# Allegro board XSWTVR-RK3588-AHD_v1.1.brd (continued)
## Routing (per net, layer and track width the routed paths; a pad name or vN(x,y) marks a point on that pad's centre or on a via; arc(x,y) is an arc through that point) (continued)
DGND: length 236.3
  TOP w0.102: ED45.1 61.36,130.42 v1(61.65,130.71) ; 113.82,75.62 114.01,75.62 114.03,75.64 114.45,75.64 114.45,75.64
  TOP w0.127: v1(120.55,44.94) v1(125.59,44.94) 126.71,44.94 127.02,44.63 ; 116.73,42.3 112.74,46.28 ; 21.81,29.3 21.81,28.74
  TOP w0.203: 0.66,104.89 0.61,104.84 0.61,101.31 0.66,101.26 ; 159.12,73.23 159.17,73.18 159.17,68.89 ; 159.17,58.34 159.17,62.4
  TOP w0.254: v1(8.58,82.75) 8.59,82.74 10.31,82.74 ; v1(8.6,84.24) 8.6,84.24 10.31,84.24 ; v1(8.66,87.24) 8.66,87.24 10.31,87.24 ; v1(8.6,85.72) 8.62,85.74 10.31,85.74 ; U23.29 48.6,116.52 U23.4 ; v1(12.01,90.23) 12,90.24 9.54,90.24 J17.17
  TOP w0.305: C314.2 38.43,63.58 R238.2
  TOP w0.381: 38.02,58.69 38.58,59.24 38.58,59.24 C308.2 ; R87.1 v1(141.46,26.79)
  TOP w0.508: R8.1 143.04,75.75 143.05,75.76 ; C2.2 v2(121.81,67.3)
  L3 w0.102: 103.49,42.42 87.16,42.42 87.03,42.29 65.07,42.29 ; 85.74,44.29 85.74,44.29 85.75,44.3 98.15,44.3 98.34,44.1 99.24,44.1 99.42,44.29 99.75,44.29 99.99,44.05 100.78,44.05 101.02,44.29 101.37,44.29 v1(101.48,44.17) 101.6,44.06 102.29,44.06 102.4,44.17 ; 55.45,43.24 102.96,43.24 ; 57.67,41.36 57.81,41.49 105.63,41.49 105.64,41.51 105.67,41.51
  L3 w0.127: 59.14,133.08 59.14,133.08 59.14,125.3 59.18,125.26 ; 121.19,89.86 121.09,89.86 ; 121.19,89.86 120.77,89.44 ; 121.19,89.86 121.36,89.86 ; 121.09,89.86 120.93,89.86 120.83,89.76 ; 121.09,89.86 120.81,89.58 ; 119.9,88.47 119.91,88.47 120.69,89.24 120.74,89.24 121.36,89.86 ; 123.34,94.51 123.34,96.07 123.33,96.08 123.33,96.16 ; 69.66,44.28 83.34,44.28 ; 121.36,89.86 122.98,91.48
  BOTTOM w0.102: 57.72,110.08 51.78,110.08
  BOTTOM w0.127: Q21.2 69.26,34.49 69.26,34.35 69.07,34.15 69.07,33.87 69.08,33.85 ; 58.28,33.54 58.06,33.77 ; 58.28,33.54 58.28,33.93 ; 58.28,33.54 58.28,30.75 58.23,30.69
  BOTTOM w0.508: 47.83,52.36 47.83,51.8 48,51.62 D6.2 ; v2(49.75,28.07) C217.2 ; C155.2 v2(133.38,29.16)
  vias: v1(0.71,154.78) v1(0.71,152.75) v1(0.71,150.72) v1(0.71,148.69) v1(0.71,146.65) v1(0.71,144.62) v1(0.71,142.59) v1(0.71,140.56) v1(0.71,138.53) v1(0.71,136.49) v1(0.71,134.46) v1(0.71,132.43) v1(0.71,130.4) v1(0.71,128.37) v1(0.71,126.33) v1(0.71,124.3) v1(0.71,122.27) v1(0.71,120.24) v1(0.71,118.21) v1(0.71,116.17) v1(0.71,114.14) v1(0.71,112.11) v1(0.71,110.08) v1(0.71,108.05) v1(0.71,99.39) v1(0.71,97.36) v1(0.71,95.33) v1(0.71,93.29) v1(0.71,91.26) v1(0.71,89.23) v1(0.71,87.2) v1(0.71,85.17) v1(0.71,83.13) v1(0.71,81.1) v1(0.71,79.07) v1(0.71,77.04) v1(0.71,75.01) v1(0.71,72.97) v1(0.71,70.94) v1(0.71,68.91) v1(0.71,66.88) v1(0.71,64.85) v1(0.71,62.81) v1(0.71,60.78) v1(0.71,58.75) v1(0.71,56.72) v1(0.71,54.69) v1(0.71,52.65) v1(0.71,50.62) v1(0.71,48.59) v1(0.71,46.56) v1(0.71,44.53) v1(0.71,42.49) v1(0.71,40.46) v1(0.71,38.43) v1(0.71,36.4) v1(0.71,34.37) v1(0.71,32.33) v1(0.71,30.3) v1(0.71,28.27) v1(0.71,26.24) v1(0.71,24.21) v1(0.71,22.17) v1(0.71,20.14) v1(0.71,18.11) v1(0.71,16.08) v1(0.71,14.05) v1(0.71,12.01) v1(0.71,9.98) v1(0.71,7.95) v1(0.71,5.92) v1(0.81,156.81) v1(1.41,1.98) v1(1.9,158.53) v1(2.54,127.61) v1(2.54,125.58) v1(2.54,123.55) v1(2.54,121.52) v1(2.54,119.48) v1(2.66,152.58) v1(2.66,150.55) v1(2.66,148.52) v1(2.66,146.48) v1(2.66,144.45) v1(2.66,142.42) v1(2.76,140.22) v1(2.76,138.19) v1(2.76,136.16) v1(2.76,134.13) v1(2.76,132.1) v1(3.12,117.54) v1(3.09,0.84) v1(3.79,159.28) v1(4.69,150.55) v1(4.69,148.52) v1(4.69,146.48) v1(4.69,144.45) v1(4.69,142.42) v1(4.72,108.53) v1(4.8,140.22) v1(4.8,138.19) v1(4.8,136.16) v1(4.8,134.13) v1(4.8,132.1) v1(5.12,0.71) v1(5.15,117.4) v1(5.82,159.29) v1(5.89,91.2) v1(5.89,89.16) v1(5.89,87.13) v1(5.89,85.1) v1(5.89,83.07) v1(6.42,54.62) v1(6.39,53.61) v1(6.73,152.58) v1(6.73,150.55) v1(6.73,148.52) v1(6.73,146.48) v1(6.73,144.45) v1(6.73,142.42) v1(6.83,140.22) v1(6.83,138.19) v1(6.83,136.16) v1(6.83,134.13) v1(6.83,132.1) v1(6.75,108.53) v1(7.18,117.4) v1(7.15,0.71) v1(7.64,80.54) v1(7.85,159.29) v1(7.89,33.51) v1(8.76,156.64) v1(8.76,154.61) v1(8.76,152.58) v1(8.76,150.55) v1(8.76,148.52) v1(8.76,146.48) v1(8.76,144.45) v1(8.76,142.42) v1(8.78,108.53) v1(8.86,140.22) v1(8.86,138.19) v1(8.86,136.16) v1(8.86,134.13) v1(8.86,132.1) v1(9.22,117.4) v1(9.2,92.84) v1(9.18,0.71) v1(9.67,80.54) v1(9.82,115.46) v1(9.83,55.42) v1(9.88,159.29) v1(10.37,96.35) v1(10.62,53.54) v1(10.79,156.64) v1(10.79,154.61) v1(10.79,152.58) v1(10.79,150.55) v1(10.79,148.52) v1(10.79,146.48) v1(10.79,144.45) v1(10.79,142.42) v1(10.89,140.22) v1(10.89,134.13) v1(10.89,132.1) v1(11.23,92.84) v1(11.3,123.13) v1(11.33,117.4) v1(11.7,80.54) v1(11.79,124.78) v1(11.91,159.29) v1(12.31,99.5) v1(12.36,96.74) v1(12.59,53.05) v1(12.82,156.64) v1(12.82,154.61) v1(12.82,152.58) v1(12.82,150.55) v1(12.82,148.52) v1(12.82,146.48) v1(12.82,144.45) v1(12.82,142.42) v1(12.92,140.22) v1(12.92,134.13) v1(12.92,132.1) v1(12.85,108.53) v1(12.88,91.66) v1(13.12,90.59) v1(13.33,123.13) v1(13.25,0.71) v1(13.36,117.4) v1(13.5,104.11) v1(13.83,124.78) v1(13.79,85.7) v1(13.77,84.21) v1(13.76,82.69) v1(13.81,81.25) v1(13.76,8.1) v1(13.76,7.34) v1(13.76,6.57) v1(13.76,5.81) v1(13.85,87.39) v1(13.95,159.29) v1(14.21,102.21) v1(14.26,8.67) v1(14.39,30.01) v1(14.42,28.94) v1(14.41,27.97) v1(14.47,98.02) v1(14.51,26.61) v1(14.51,25.09) v1(14.51,23.41) v1(14.53,22.4) v1(14.46,20.38) v1(14.63,92.7) v1(14.83,7.34) v1(14.83,6.57) v1(14.83,5.81) v1(14.85,156.64) v1(14.85,154.61) v1(14.85,152.58) v1(14.85,150.55) v1(14.85,148.52) v1(14.85,146.48) v1(14.85,144.45) v1(14.85,142.42) v1(14.91,11.46) v1(14.96,138.19) v1(14.96,134.13) v1(15.04,98.02) v1(15,62.7) v1(15,7.9) v1(15.28,0.71) v1(15.36,123.13) v1(15.4,117.4) v1(15.54,8.44) v1(15.86,124.78) v1(15.9,94.29) v1(15.86,92.18) v1(15.89,91.02) v1(15.9,88.74) v1(15.87,87.67) v1(15.98,159.29) v1(15.95,89.88) v1(16.04,85.68) v1(16.05,82.66) v1(16.11,81.34) v1(16.09,12.11) v1(16.16,41.82) v1(16.26,110.8) v1(16.33,73.69) v1(16.34,35.83) v1(16.41,87.02) v1(16.49,20.38) v1(16.59,84.24) v1(16.61,27.92) v1(16.61,26.61) v1(16.61,25.1) v1(16.73,41.82) v1(16.75,139.68) v1(16.89,156.64) v1(16.89,154.61) v1(16.89,152.58) v1(16.89,150.55) v1(16.89,148.52) v1(16.89,146.48) v1(16.89,144.45) v1(16.89,142.42) v1(16.86,132.83) v1(16.86,130.8) v1(17,13.27) v1(17.07,123.14) v1(17.16,98.48) v1(17.36,137.75) v1(17.41,124.78) v1(17.43,117.4) v1(17.6,81.07) v1(17.57,73.71) v1(17.73,36.17) v1(17.75,61.97) v1(17.81,60.24) v1(17.94,10.06) v1(18.01,159.29) v1(18,77.2) v1(18.11,138.18) v1(18.25,121.29) v1(18.25,119.25) v1(18.29,110.8) v1(18.4,13.94) v1(18.53,27.27) v1(18.52,20.38) v1(18.64,87.05) v1(18.64,85.95) v1(18.65,122.61) v1(18.66,99.8) v1(18.67,36.15) v1(18.92,156.64) v1(18.92,154.61) v1(18.92,152.58) v1(18.92,150.55) v1(18.92,148.52) v1(18.92,146.48) v1(18.92,144.45) v1(18.92,142.42) v1(18.94,82.91) v1(18.94,30.57) v1(18.94,29.45) v1(18.89,28.51) v1(18.96,81.38) v1(19.02,76.27) v1(18.96,26.14) v1(18.96,23.99) v1(18.97,22.92) v1(18.97,21.78) v1(18.99,11.8) v1(19.07,85.52) v1(19.11,84) v1(19.2,96.57) v1(19.32,55.4) v1(19.34,0.71) v1(19.35,53.7) v1(19.66,87.05) v1(19.8,122.59) v1(19.87,64.06) v1(19.92,13.94) v1(20.04,159.29) v1(19.95,82.91) v1(19.97,81.48) v1(20.09,85.52) v1(20.13,84) v1(20.32,110.8) v1(20.35,51.44) v1(20.64,55.38) v1(20.56,27.36) v1(20.55,20.38) v1(20.7,99.8) v1(20.72,63.01) v1(20.77,45.31) v1(20.86,12.58) v1(20.95,156.64) v1(20.95,154.61) v1(20.95,152.58) v1(20.95,150.55) v1(20.95,148.52) v1(20.95,146.48) v1(20.95,144.45) v1(20.95,142.42) v1(21.03,52.52) v1(21.11,85.52) v1(21.14,84) v1(21.19,137.61) v1(21.44,13.94) v1(21.38,0.71) v1(21.51,103.96) v1(21.63,122.53) v1(21.64,81.48) v1(21.77,43.54) v1(21.77,32.63) v1(21.92,77.92) v1(22.03,134.47) v1(21.98,82.91) v1(21.95,76.57) v1(22.01,27.95) v1(22.07,159.29) v1(22.16,84) v1(22.19,66.35) v1(22.16,24.65) v1(22.19,23.42) v1(22.26,22.32) v1(22.35,110.69) v1(22.53,40.88) v1(22.73,99.8) v1(22.7,87.05) v1(22.78,122.56) v1(22.85,82.47) v1(22.88,81.38) v1(22.9,12.58) v1(22.98,156.64) v1(22.98,154.61) v1(22.98,152.58) v1(22.98,150.55) v1(22.98,148.52) v1(22.98,146.48) v1(22.98,144.45) v1(22.98,142.42) v1(23.02,65.45) v1(22.99,53.42) v1(23.04,40.87) v1(22.98,37.27) v1(22.97,13.94) v1(23.05,51.41) v1(23.09,49.7) v1(23.29,30.08) v1(23.4,139) v1(23.41,34.47) v1(23.41,0.71) v1(23.54,103.96) v1(23.57,40.86) v1(23.72,87.05) v1(23.92,122.58) v1(23.87,96.55) v1(23.87,82.47) v1(23.9,81.38) v1(24.01,32.67) v1(24.11,159.29) v1(24.15,85.52) v1(24.49,13.94) v1(24.74,87.05) v1(24.76,99.8) v1(24.91,81.38) v1(24.93,12.58) v1(25.01,156.64) v1(25.01,154.61) v1(25.01,152.58) v1(25.01,150.55) v1(25.01,148.52) v1(25.01,146.48) v1(25.01,144.45) v1(25.02,42.85) v1(25.14,84.01) v1(25.05,40.82) v1(25.19,122.59) v1(25.17,85.52) v1(25.4,28.41) v1(25.42,27.56) v1(25.41,26.74) v1(25.4,22.85) v1(25.44,0.71) v1(25.58,103.96) v1(25.75,87.05) v1(25.83,76.55) v1(25.85,77.87) v1(25.97,127.1) v1(26.02,13.94) v1(26.14,159.29) v1(26.13,84.26) v1(26.19,85.52) v1(26.16,51.09) v1(26.49,67.24) v1(26.5,65.94) v1(26.5,26.75) v1(26.79,99.8) v1(26.77,87.05) v1(26.92,82.47) v1(26.85,22.85) v1(26.96,12.58) v1(27.05,156.64) v1(27.05,154.61) v1(27.05,152.58) v1(27.05,150.55) v1(27.05,148.52) v1(27.05,146.48) v1(27.05,144.45) v1(27.2,85.52) v1(27.15,84.26) v1(27.33,36.42) v1(27.33,34.39) v1(27.42,122.59) v1(27.42,43.91) v1(27.54,13.94) v1(27.47,0.71) v1(27.61,103.96) v1(27.57,26.74) v1(27.73,81.36) v1(27.78,87.05) v1(27.93,82.47) v1(27.86,43.17) v1(27.98,124.64) v1(28,38.34) v1(28.13,49.07) v1(28.17,159.29) v1(28.22,85.52) v1(28.15,84.09) v1(28.42,25.67) v1(28.42,24.15) v1(28.61,75.77) v1(28.65,53.89) v1(28.8,87.05) v1(28.78,51.69) v1(28.8,45.77) v1(28.77,31.58) v1(28.95,82.47) v1(28.98,81.38) v1(28.95,66) v1(28.99,12.58) v1(29.08,156.64) v1(29.08,154.61) v1(29.08,152.58) v1(29.08,150.55) v1(29.08,148.52) v1(29.08,146.48) v1(29.08,144.45) v1(29.14,124.63) v1(29.06,13.94) v1(29.18,122.85) v1(29.23,85.52) v1(29.16,84) v1(29.21,27.42) v1(29.3,44.61) v1(29.49,135.3) v1(29.5,0.71) v1(29.6,55.78) v1(29.73,28.14) v1(29.82,87.05) v1(29.77,21.66) v1(29.96,82.47) v1(30.14,75.58) v1(30.14,53.17) v1(30.14,52.03) v1(30.2,159.29) v1(30.18,84) v1(30.16,55.76) v1(30.25,85.52) v1(30.36,124.65) v1(30.38,122.86) v1(30.41,109.64) v1(30.39,68.02) v1(30.45,50.78) v1(30.59,13.94) v1(30.71,55.77) v1(30.83,87.05) v1(30.75,28.27) v1(30.87,41.21) v1(30.94,37.97) v1(30.86,36.18) v1(30.85,34.73) v1(30.85,33.36) v1(30.86,24.16) v1(30.98,82.47) v1(31.01,81.38) v1(31.02,12.58) v1(31.11,156.64) v1(31.11,154.61) v1(31.11,152.58) v1(31.11,150.55) v1(31.11,148.52) v1(31.11,146.48) v1(31.11,144.45) v1(31.19,84) v1(31.27,85.52) v1(31.32,49.6) v1(31.53,124.65) v1(31.46,75.57) v1(31.58,122.86) v1(31.85,87.05) v1(32,82.47) v1(32.02,81.38) v1(31.96,40.91) v1(32.11,112.37) v1(32.11,13.94) v1(32.23,159.29) v1(32.21,84) v1(32.28,85.52) v1(32.4,65.31) v1(32.73,124.64) v1(32.69,38.16) v1(32.82,122.89) v1(33.01,82.47) v1(33.04,81.38) v1(33.01,8.86) v1(33.01,8.1) v1(33.01,7.34) v1(33.01,6.57) v1(33.01,5.81) v1(33.14,156.64) v1(33.14,154.61) v1(33.14,152.58) v1(33.14,150.55) v1(33.14,148.52) v1(33.14,146.48) v1(33.14,144.45) v1(33.06,12.58) v1(33.22,84) v1(33.3,85.52) v1(33.54,40.86) v1(33.64,13.94) v1(33.57,0.71) v1(33.74,44.08) v1(33.8,75.05) v1(33.92,124.67) v1(34.01,122.89) v1(34.03,82.47) v1(34.06,81.38) v1(34.11,52.92) v1(34.09,33.36) v1(34.07,10.81) v1(34.07,8.86) v1(34.07,8.1) v1(34.07,7.34) v1(34.07,6.57) v1(34.07,5.81) v1(34.24,84) v1(34.27,159.29) v1(34.3,102.92) v1(34.31,85.52) v1(34.67,75.88) v1(34.89,38.07) v1(35.04,40.84) v1(35.09,33.86) v1(35.09,12.58) v1(35.17,156.64) v1(35.17,154.61) v1(35.17,152.58) v1(35.17,150.55) v1(35.17,148.52) v1(35.17,146.48) v1(35.17,144.45) v1(35.18,124.68) v1(35.16,13.94) v1(35.39,55.35) v1(35.73,103.88) v1(35.79,34.63) v1(36.3,159.29) v1(36.41,122.7) v1(36.52,50.55) v1(36.57,40.81) v1(36.68,13.94) v1(37.21,156.64) v1(37.21,154.61) v1(37.21,152.58) v1(37.21,150.55) v1(37.21,148.52) v1(37.21,146.48) v1(37.21,144.45) v1(37.49,36.2) v1(37.62,125.68) v1(37.6,122.94) v1(37.6,37.67) v1(37.63,8.86) v1(37.63,0.71) v1(37.83,58.25) v1(38.03,10.85) v1(38.33,159.29) v1(38.32,36.21) v1(38.39,58.23) v1(38.71,102.85) v1(38.71,72.07) v1(38.69,69.82) v1(38.7,67.31) v1(38.7,65.95) v1(38.84,122.91) v1(38.94,58.24) v1(38.89,37.54) v1(39.24,156.64) v1(39.24,154.61) v1(39.24,152.58) v1(39.24,150.55) v1(39.24,148.52) v1(39.24,146.48) v1(39.24,144.45) v1(39.24,42.1) v1(39.66,0.71) v1(39.98,53.13) v1(40.12,125.9) v1(40.05,11.02) v1(40.36,159.29) v1(40.42,14.28) v1(40.69,37.8) v1(40.76,37.15) v1(40.98,104.89) v1(41.11,54.93) v1(41.19,51.74) v1(41.27,156.64) v1(41.27,154.61) v1(41.27,152.58) v1(41.27,150.55) v1(41.27,148.52) v1(41.27,146.48) v1(41.27,144.45) v1(41.31,38.64) v1(41.7,0.71) v1(41.92,28.04) v1(41.92,26.77) v1(41.92,25.5) v1(41.92,24.23) v1(42.13,55.3) v1(42.08,11.02) v1(42.2,16.37) v1(42.34,125.46) v1(42.39,159.29) v1(43.14,122.62) v1(43.19,28.04) v1(43.19,26.77) v1(43.19,25.5) v1(43.19,24.23) v1(43.3,156.64) v1(43.3,154.61) v1(43.3,152.58) v1(43.3,150.55) v1(43.3,148.52) v1(43.3,146.48) v1(43.3,144.45) v1(43.34,126.3) v1(43.29,46.41) v1(43.73,0.71) v1(44.03,122.6) v1(44.1,11.27) v1(44.43,159.29) v1(44.49,41.05) v1(44.46,28.04) v1(44.46,26.77) v1(44.46,25.5) v1(44.46,24.23) v1(44.46,14.74) v1(45.33,156.64) v1(45.33,154.61) v1(45.33,152.58) v1(45.33,150.55) v1(45.33,148.52) v1(45.33,146.48) v1(45.33,144.45) v1(45.67,42.17) v1(45.73,28.04) v1(45.73,26.77) v1(45.73,25.5) v1(45.73,24.23) v1(45.76,0.71) v1(45.88,117.53) v1(45.9,16.74) v1(46.32,115.65) v1(46.38,100.33) v1(46.39,97.34) v1(46.46,159.29) v1(46.45,140.12) v1(46.47,118.92) v1(46.49,46.23) v1(46.52,41.05) v1(46.58,57.97) v1(47,28.04) v1(47,26.77) v1(47,25.5) v1(47,24.23) v1(47.37,156.64) v1(47.37,154.61) v1(47.37,152.58) v1(47.37,150.55) v1(47.37,148.52) v1(47.37,146.48) v1(47.37,144.45) v1(47.54,41.05) v1(47.57,134.36) v1(47.57,132.33) v1(47.57,130.3) v1(47.57,128.26) v1(47.55,122.96) v1(47.62,48.79) v1(47.62,46.75) v1(47.81,116.87) v1(47.81,115.81) v1(47.79,0.71) v1(47.97,33.87) v1(48.08,140.97) v1(48.43,94.84) v1(48.49,159.29) v1(48.48,97.93) v1(48.52,33.85) v1(48.59,31.69) v1(48.56,16.33) v1(48.69,126.57) v1(48.69,116.87) v1(48.68,115.83) v1(48.77,124.59) v1(48.8,122.96) v1(49.14,33.89) v1(49.29,10.29) v1(49.4,156.64) v1(49.4,154.61) v1(49.4,152.58) v1(49.4,150.55) v1(49.4,148.52) v1(49.4,146.48) v1(49.4,144.45) v1(49.51,116.9) v1(49.49,115.84) v1(50.03,13.87) v1(50.11,140.97) v1(50.08,122.96) v1(50.09,40.12) v1(50.17,44.11) v1(50.52,159.29) v1(50.86,124.83) v1(51.32,123.01) v1(51.43,156.64) v1(51.43,154.61) v1(51.43,152.58) v1(51.43,150.55) v1(51.43,148.52) v1(51.43,146.48) v1(51.43,144.45) v1(51.71,112.07) v1(51.69,46.75) v1(51.69,44.72) v1(51.74,11.74) v1(51.83,41.47) v1(51.86,39.9) v1(51.89,8.77) v1(51.86,0.71) v1(52.14,140.97) v1(52.24,44.24) v1(52.25,8.1) v1(52.25,7.34) v1(52.25,6.57) v1(52.25,5.81) v1(52.35,105.97) v1(52.55,159.29) v1(52.89,9.28) v1(53,124.85) v1(53.32,8.1) v1(53.32,7.34) v1(53.32,6.57) v1(53.32,5.81) v1(53.39,126.92) v1(53.46,156.64) v1(53.46,154.61) v1(53.46,152.58) v1(53.46,150.55) v1(53.46,148.52) v1(53.46,146.48) v1(53.46,144.45) v1(53.46,142.42) v1(53.48,39.85) v1(53.63,41.5) v1(53.66,120.86) v1(53.74,30.22) v1(53.83,43.97) v1(53.88,14.26) v1(53.95,140.04) v1(53.95,126.09) v1(53.97,48.75) v1(53.97,48.2) v1(54.14,16.4) v1(54.11,12.25) v1(54.18,121.64) v1(54.18,120.87) v1(54.29,129.93) v1(54.38,138.05) v1(54.38,136.02) v1(54.38,133.99) v1(54.38,131.96) v1(54.36,105.97) v1(54.42,49.13) v1(54.59,159.29) v1(55.1,49.14) v1(55.15,122.06) v1(55.18,39.83) v1(55.41,127.08) v1(55.4,41.49) v1(55.49,156.64) v1(55.49,154.61) v1(55.49,152.58) v1(55.49,150.55) v1(55.49,148.52) v1(55.49,146.48) v1(55.49,144.45) v1(55.49,142.42) v1(55.47,139.58) v1(55.47,137.55) v1(55.47,135.52) v1(55.47,133.49) v1(55.47,131.45) v1(55.53,124.91) v1(55.76,49.08) v1(56.3,129.6) v1(56.28,105.97) v1(56.33,48.18) v1(56.34,47.62) v1(56.46,120.51) v1(56.62,159.29) v1(56.71,127.68) v1(56.66,126.24) v1(56.9,113.1) v1(56.91,112.42) v1(56.86,40.62) v1(56.92,39.82) v1(57.2,153.31) v1(57.2,151.28) v1(57.2,149.25) v1(57.2,147.21) v1(57.2,145.18) v1(57.2,143.15) v1(57.2,141.12) v1(57.2,139.09) v1(57.2,137.05) v1(57.2,135.02) v1(57.2,132.99) v1(57.2,130.96) v1(57.2,128.93) v1(57.17,47.62) v1(57.19,41.25) v1(57.55,120.83) v1(57.55,118.8) v1(57.76,44.17) v1(57.95,0.71) v1(58.11,151.64) v1(58.11,149.61) v1(58.11,147.58) v1(58.11,145.54) v1(58.11,143.51) v1(58.11,141.48) v1(58.11,139.45) v1(58.1,38.57) v1(58.27,105.97) v1(58.41,154.94) v1(58.42,153.65) v1(58.65,159.29) v1(59.39,109.97) v1(59.44,11.36) v1(59.47,141.18) v1(59.64,61.06) v1(59.64,58.13) v1(59.88,155.06) v1(59.98,0.71) v1(60.16,120.44) v1(60.22,26.74) v1(60.28,105.97) v1(60.68,159.29) v1(60.73,21.13) v1(61.5,141.21) v1(61.67,61.06) v1(61.67,58.13) v1(61.8,109.34) v1(61.91,154.94) v1(61.95,110.45) v1(62.02,0.71) v1(62.13,105.97) v1(62.39,31.07) v1(62.43,20.01) v1(62.43,17.98) v1(62.47,129.99) v1(62.58,128.75) v1(62.58,112.49) v1(63.15,122.88) v1(63.49,11.57) v1(63.7,61.06) v1(64.05,0.71) v1(64.2,105.97) v1(64.3,15.15) v1(64.4,109.3) v1(64.47,25.58) v1(64.62,128.75) v1(64.62,122.65) v1(64.62,120.62) v1(64.62,118.59) v1(64.67,110.46) v1(64.67,38.34) v1(64.76,111.99) v1(64.87,142.4) v1(64.87,140.37) v1(64.87,138.34) v1(64.87,136.31) v1(64.87,134.28) v1(64.87,132.24) v1(65.55,144.53) v1(65.63,33.22) v1(65.73,61.06) v1(65.99,25.7) v1(66.08,0.71) v1(66.21,105.97) v1(66.16,33.24) v1(66.34,38.39) v1(66.65,128.75) v1(66.65,122.65) v1(66.65,120.62) v1(66.65,118.59) v1(66.71,110.46) v1(66.78,159.29) v1(66.75,147.14) v1(66.8,111.99) v1(66.83,26.45) v1(66.91,142.4) v1(66.91,140.37) v1(66.91,138.34) v1(66.91,136.31) v1(66.91,134.28) v1(66.91,132.24) v1(67.18,147.76) v1(67.26,144.51) v1(67.72,148.3) v1(67.83,109.38) v1(67.76,61.06) v1(68.02,105.97) v1(68.01,18.12) v1(68.11,0.71) v1(68.22,147.07) v1(68.26,148.84) v1(68.5,11.89) v1(68.64,38.9) v1(68.68,128.75) v1(68.68,120.62) v1(68.68,118.59) v1(68.74,110.46) v1(68.81,159.29) v1(68.79,149.39) v1(68.76,147.61) v1(68.83,111.99) v1(68.82,33.88) v1(68.84,23.21) v1(68.94,142.4) v1(68.94,140.37) v1(68.94,138.34) v1(68.94,136.31) v1(68.94,134.28) v1(68.94,132.24) v1(69.23,156.93) v1(69.23,155.62) v1(69.22,154.99) v1(69.2,154.38) v1(69.16,150.05) v1(69.28,152.69) v1(69.31,151.73) v1(69.31,150.8) v1(69.3,148.15) v1(69.34,28.16) v1(69.81,148.72) v1(69.8,61.06) v1(70.08,157.17) v1(70.09,105.97) v1(70.2,149.37) v1(70.19,22.31) v1(70.44,150.09) v1(70.35,38.92) v1(70.44,27.26) v1(70.53,153.51) v1(70.53,152.75) v1(70.53,151.99) v1(70.53,151.23) v1(70.53,12.01) v1(70.6,154.97) v1(70.6,154.28) v1(70.68,156.1) v1(70.71,128.75) v1(70.71,124.68) v1(70.71,120.62) v1(70.71,118.59) v1(70.71,37.19) v1(70.84,159.29) v1(70.84,157.27) v1(70.97,142.4) v1(70.97,140.37) v1(70.97,138.34) v1(70.97,136.31) v1(70.97,134.28) v1(70.97,132.24) v1(71.08,13.23) v1(71.44,156.1) v1(71.49,8.1) v1(71.49,7.34) v1(71.49,6.57) v1(71.49,5.81) v1(71.6,157.27) v1(71.83,61.06) v1(71.91,21.94) v1(72.14,149.2) v1(72.13,148.44) v1(72.2,156.1) v1(72.19,147.68) v1(72.17,105.97) v1(72.16,27.26) v1(72.18,0.71) v1(72.36,157.27) v1(72.45,149.9) v1(72.46,34.51) v1(72.48,23.32) v1(72.56,147.01) v1(72.56,8.1) v1(72.56,7.34) v1(72.56,6.57) v1(72.56,5.81) v1(72.74,120.62) v1(72.74,118.59) v1(72.69,11.99) v1(72.87,159.29) v1(72.89,144.47) v1(72.96,156.1) v1(73,142.4) v1(73,140.37) v1(73,138.34) v1(73,136.31) v1(73,134.28) v1(73,132.24) v1(73.13,157.27) v1(73.09,150.32) v1(73.44,149.15) v1(73.35,148.39) v1(73.62,147.68) v1(73.72,156.1) v1(73.72,144.46) v1(73.84,150.49) v1(73.86,61.06) v1(73.89,58.97) v1(73.94,56.9) v1(73.94,54.87) v1(73.94,51.24) v1(73.96,52.95) v1(73.96,50.02) v1(73.99,48.15) v1(74.01,46.24) v1(74.13,105.97) v1(74.16,147.14) v1(74.36,13.09) v1(74.49,156.1) v1(74.48,144.43) v1(74.53,39.09) v1(74.62,150.5) v1(74.65,157.27) v1(74.71,111.83) v1(74.74,110.65) v1(74.78,120.62) v1(74.78,118.59) v1(74.91,159.29) v1(75.01,149.07) v1(75.03,142.4) v1(75.03,140.37) v1(75.03,138.34) v1(75.03,136.31) v1(75.03,134.28) v1(75.03,132.24) v1(75.25,156.1) v1(75.33,23.36) v1(75.36,150.48) v1(75.61,32.66) v1(75.77,144.7) v1(75.89,61.06) v1(76,156.21) v1(76,150.49) v1(76,149.07) v1(76.07,58.95) v1(76.07,56.91) v1(76.07,54.88) v1(76.1,52.97) v1(76.07,51.25) v1(76.1,50.03) v1(76.12,48.17) v1(76.19,105.97) v1(76.15,46.25) v1(76.24,0.71) v1(76.33,148.21) v1(76.39,13.09) v1(76.64,150.5) v1(76.69,23.08) v1(76.77,111.84) v1(76.77,110.65) v1(76.76,11.99) v1(76.94,159.29) v1(77.14,150.89) v1(77.27,148.14) v1(77.44,156.01) v1(77.44,155.25) v1(77.44,154.49) v1(77.44,153.72) v1(77.44,152.96) v1(77.44,152.2) v1(77.44,151.44) v1(77.54,156.76) v1(77.53,140.07) v1(77.5,35.41) v1(77.63,143.88) v1(77.55,34.17) v1(77.73,148.86) v1(77.7,27.02) v1(77.78,149.63) v1(77.92,61.06) v1(77.95,157.4) v1(78.1,58.95) v1(78.1,56.91) v1(78.1,54.88) v1(78.13,52.97) v1(78.1,51.25) v1(78.13,50.03) v1(78.18,105.97) v1(78.15,48.17) v1(78.18,46.25) v1(78.16,17.72) v1(78.32,150.17) v1(78.25,130.36) v1(78.25,128.33) v1(78.25,126.29) v1(78.25,124.26) v1(78.28,32.1) v1(78.27,0.71) v1(78.4,36.37) v1(78.61,157.79) v1(78.8,111.84) v1(78.8,110.65) v1(78.86,155.88) v1(78.86,155.12) v1(78.86,154.35) v1(78.86,153.59) v1(78.86,152.83) v1(78.86,152.07) v1(78.86,151.31) v1(78.86,150.71) v1(78.97,159.29) v1(79.11,39.47) v1(79.42,151.63) v1(79.44,142.95) v1(79.47,150.87) v1(79.49,35.82) v1(79.73,150.16) v1(79.69,130.77) v1(79.72,128.79) v1(79.72,124.73) v1(79.72,120.66) v1(79.72,118.63) v1(79.72,116.6) v1(79.65,40.02) v1(79.96,61.06) v1(80.14,58.95) v1(80.14,56.91) v1(80.14,54.88) v1(80.14,51.25) v1(80.18,149.54) v1(80.23,139.33) v1(80.23,137.3) v1(80.23,135.27) v1(80.23,133.23) v1(80.21,105.97) v1(80.16,52.97) v1(80.16,50.03) v1(80.19,48.17) v1(80.21,46.25) v1(80.18,17.49) v1(80.3,0.71) v1(80.63,148.93) v1(80.84,151.63) v1(80.85,148.2) v1(80.87,147.43) v1(80.87,146.67) v1(80.87,145.91) v1(80.86,145.02) v1(81,159.29) v1(80.96,150.88) v1(81.17,130.02) v1(81.43,150.28) v1(81.76,128.79) v1(81.76,124.73) v1(81.76,120.66) v1(81.76,118.63) v1(81.76,116.6) v1(81.8,38.36) v1(81.86,149.65) v1(81.99,61.06) v1(82.14,148.94) v1(82.13,22.48) v1(82.24,105.97) v1(82.17,58.95) v1(82.17,56.91) v1(82.17,54.88) v1(82.19,52.97) v1(82.17,51.25) v1(82.19,50.03) v1(82.22,48.17) v1(82.24,46.25) v1(82.28,148.19) v1(82.29,147.43) v1(82.29,146.67) v1(82.3,145.96) v1(82.3,144.75) v1(82.26,139.33) v1(82.26,137.3) v1(82.26,135.27) v1(82.26,133.23) v1(82.28,27.02) v1(82.34,0.71) v1(82.74,34.41) v1(83.11,144.76) v1(83.2,130.02) v1(83.31,145.89) v1(83.56,39.31) v1(83.79,128.79) v1(83.79,124.73) v1(83.79,120.66) v1(83.79,118.63) v1(83.79,116.6) v1(84.02,61.06) v1(84.15,105.97) v1(84.2,58.95) v1(84.2,56.91) v1(84.2,54.88) v1(84.22,52.97) v1(84.2,51.25) v1(84.22,50.03) v1(84.15,39.28) v1(84.19,22.42) v1(84.3,141.36) v1(84.3,139.33) v1(84.3,137.3) v1(84.3,135.27) v1(84.3,133.23) v1(84.25,48.17) v1(84.27,46.25) v1(84.32,34.67) v1(84.29,27.09) v1(84.37,0.71) v1(84.66,44.17) v1(85.02,144.79) v1(85.07,159.29) v1(85.23,130.02) v1(85.39,23.38) v1(85.52,154.39) v1(85.51,152.39) v1(85.51,150.36) v1(85.6,148.33) v1(85.6,144.14) v1(85.99,105.97) v1(86.05,61.06) v1(86.23,58.95) v1(86.23,56.91) v1(86.23,54.88) v1(86.24,53.02) v1(86.33,141.36) v1(86.33,139.33) v1(86.33,137.3) v1(86.33,135.27) v1(86.33,133.23) v1(86.31,49.99) v1(86.35,48.17) v1(86.37,46.25) v1(86.4,0.71) v1(86.75,152.37) v1(86.75,150.34) v1(86.82,145.74) v1(86.79,34.18) v1(87.1,159.29) v1(87.14,130.62) v1(87.06,11.21) v1(87.15,155.85) v1(87.59,144.78) v1(87.72,152.13) v1(87.78,155.03) v1(87.85,128.79) v1(87.85,124.73) v1(87.85,120.66) v1(87.85,118.63) v1(87.85,116.6) v1(87.91,111.06) v1(87.86,23.79) v1(87.99,105.97) v1(88.08,61.06) v1(88.09,20.11) v1(88.09,19.42) v1(88.26,58.95) v1(88.26,56.91) v1(88.26,54.88) v1(88.26,53.02) v1(88.36,141.36) v1(88.36,139.33) v1(88.36,137.3) v1(88.36,135.27) v1(88.36,133.23) v1(88.38,48.17) v1(88.4,46.25) v1(88.46,32.73) v1(88.73,14.39) v1(88.85,145.74) v1(89.01,19.04) v1(89.13,159.29) v1(89.08,130.02) v1(89.16,24.26) v1(89.27,151.49) v1(89.25,150.14) v1(89.36,38.05) v1(89.62,144.78) v1(89.65,128.07) v1(89.65,126.04) v1(89.65,124) v1(89.94,111.06) v1(90.12,61.06) v1(90.16,15.82) v1(90.2,11.41) v1(90.3,58.95) v1(90.3,56.91) v1(90.3,54.88) v1(90.31,53.06) v1(90.31,50.04) v1(90.39,141.36) v1(90.39,139.33) v1(90.39,137.3) v1(90.39,135.27) v1(90.39,133.23) v1(90.41,48.17) v1(90.41,46.31) v1(90.46,0.71) v1(90.74,8.1) v1(90.74,7.34) v1(90.74,6.57) v1(90.74,5.81) v1(90.77,118.25) v1(90.91,125.59) v1(90.91,123.56) v1(90.91,121.52) v1(91.34,129.61) v1(91.67,15.13) v1(91.8,8.1) v1(91.8,7.34) v1(91.8,6.57) v1(91.8,5.81) v1(91.94,105.99) v1(91.97,111.06) v1(92.15,61.06) v1(92.19,50.07) v1(92.33,58.95) v1(92.33,56.91) v1(92.33,54.88) v1(92.27,48.11) v1(92.34,46.24) v1(92.42,141.36) v1(92.42,139.33) v1(92.42,137.3) v1(92.42,133.23) v1(92.42,25.58) v1(92.63,118.07) v1(92.81,128.21) v1(92.99,28.98) v1(93.65,115.37) v1(94.01,111.06) v1(93.97,105.99) v1(94.1,130.32) v1(94.12,52.89) v1(94.12,50.85) v1(94.18,61.06) v1(94.19,58.94) v1(94.18,56.91) v1(94.18,54.91) v1(94.15,48.94) v1(94.17,47) v1(94.46,141.36) v1(94.46,139.33) v1(94.46,137.3) v1(94.83,128.42) v1(95.23,159.29) v1(95.2,143.43) v1(95.45,156.41) v1(95.45,154.38) v1(95.45,152.35) v1(95.45,129.99) v1(95.45,125.93) v1(95.45,123.9) v1(96.04,111.06) v1(96,105.99) v1(96.2,56.94) v1(96.2,54.91) v1(96.15,52.89) v1(96.15,50.85) v1(96.18,48.94) v1(96.2,47) v1(96.52,112.5) v1(96.56,0.71) v1(96.88,35.93) v1(96.99,11.97) v1(97.26,159.29) v1(97.4,143.94) v1(97.4,141.9) v1(97.4,139.87) v1(97.4,137.84) v1(97.4,135.81) v1(97.4,133.78) v1(97.4,125.65) v1(97.4,123.62) v1(97.4,121.58) v1(97.4,119.55) v1(97.4,117.52) v1(97.48,156.41) v1(97.48,154.38) v1(97.48,152.35) v1(97.48,148.28) v1(97.96,111.06) v1(98.04,105.99) v1(98.24,56.94) v1(98.24,54.91) v1(98.19,52.89) v1(98.19,50.85) v1(98.21,48.94) v1(98.24,47) v1(98.38,112.33) v1(98.59,0.71) v1(98.88,16.55) v1(99.29,159.29) v1(99.52,156.41) v1(99.52,154.38) v1(99.52,152.35) v1(99.52,148.28) v1(99.52,146.25) v1(99.52,144.22) v1(99.52,142.19) v1(99.52,140.15) v1(99.52,138.12) v1(99.52,136.09) v1(99.52,134.06) v1(99.52,132.03) v1(99.52,127.96) v1(99.52,125.93) v1(99.52,123.9) v1(99.52,121.87) v1(99.52,119.83) v1(99.52,117.8) v1(99.52,115.28) v1(99.71,112.48) v1(100.03,11.97) v1(100.07,105.99) v1(100.22,52.89) v1(100.22,50.85) v1(100.24,48.94) v1(100.26,111.55) v1(100.27,56.94) v1(100.27,54.91) v1(100.27,47) v1(100.64,15.54) v1(100.62,0.71) v1(101.07,26.7) v1(101.07,25.43) v1(101.07,24.16) v1(101.07,22.89) v1(101.07,21.62) v1(101.07,20.35) v1(101.32,159.29) v1(101.44,45.23) v1(101.44,13.61) v1(101.55,156.41) v1(101.55,154.38) v1(101.55,152.35) v1(101.55,150.31) v1(101.55,148.28) v1(101.55,146.25) v1(101.55,144.22) v1(101.55,142.19) v1(101.55,140.15) v1(101.55,138.12) v1(101.55,136.09) v1(101.55,134.06) v1(101.55,132.03) v1(101.55,129.99) v1(101.55,127.96) v1(101.55,125.93) v1(101.55,123.9) v1(101.55,121.87) v1(101.55,119.83) v1(101.55,117.8) v1(101.55,115.28) v1(101.74,112.48) v1(102.1,105.99) v1(102.29,111.55) v1(102.25,52.89) v1(102.25,50.85) v1(102.25,48.99) v1(102.28,47.05) v1(102.34,26.7) v1(102.34,25.43) v1(102.34,24.16) v1(102.34,22.89) v1(102.34,21.62) v1(102.34,20.35) v1(102.41,35.77) v1(102.67,15.54) v1(102.66,0.71) v1(103.08,11.97) v1(103.35,159.29) v1(103.58,156.41) v1(103.58,154.38) v1(103.58,152.35) v1(103.58,150.31) v1(103.58,148.28) v1(103.58,146.25) v1(103.58,144.22) v1(103.58,142.19) v1(103.58,140.15) v1(103.58,138.12) v1(103.58,136.09) v1(103.58,134.06) v1(103.58,132.03) v1(103.58,129.99) v1(103.58,127.96) v1(103.58,125.93) v1(103.58,123.9) v1(103.58,121.87) v1(103.58,119.83) v1(103.58,117.8) v1(103.58,115.28) v1(103.59,45.28) v1(103.61,44.12) v1(103.61,26.7) v1(103.61,25.43) v1(103.61,24.16) v1(103.61,22.89) v1(103.61,21.62) v1(103.61,20.35) v1(104.13,105.99) v1(104.36,50.88) v1(104.38,48.96) v1(104.41,47.02) v1(104.7,15.54) v1(104.69,0.71) v1(104.88,26.7) v1(104.88,25.43) v1(104.88,24.16) v1(104.88,22.89) v1(104.88,21.62) v1(104.88,20.35) v1(105.39,159.29) v1(105.44,12.47) v1(105.52,45.29) v1(105.61,156.41) v1(105.61,154.38) v1(105.61,152.35) v1(105.61,150.31) v1(105.61,148.28) v1(105.61,146.25) v1(105.61,144.22) v1(105.61,142.19) v1(105.61,140.15) v1(105.61,138.12) v1(105.61,136.09) v1(105.61,125.93) v1(105.61,123.9) v1(105.61,121.87) v1(105.61,119.83) v1(105.61,117.8) v1(105.64,115.24) v1(105.6,111.68) v1(105.57,44.1) v1(105.91,62.34) v1(105.88,35.79) v1(106.15,26.7) v1(106.15,25.43) v1(106.15,24.16) v1(106.15,22.89) v1(106.15,21.62) v1(106.15,20.35) v1(106.39,50.88) v1(106.41,48.96) v1(106.44,47.02) v1(106.4,9.72) v1(106.67,16.06) v1(106.72,0.71) v1(106.99,93.72) v1(106.99,87.34) v1(106.98,63.92) v1(107.05,101.3) v1(107.05,99.33) v1(107.05,79.38) v1(107.05,72.37) v1(107.42,159.29) v1(107.42,26.7) v1(107.42,25.43) v1(107.42,24.16) v1(107.42,22.89) v1(107.42,21.62) v1(107.42,20.35) v1(107.54,45.33) v1(107.47,41.32) v1(107.64,156.41) v1(107.64,154.38) v1(107.64,152.35) v1(107.64,150.31) v1(107.64,148.28) v1(107.64,146.25) v1(107.64,144.22) v1(107.64,125.93) v1(107.64,123.9) v1(107.64,121.87) v1(107.64,119.83) v1(107.64,117.8) v1(107.63,111.68) v1(107.6,44.13) v1(107.66,142.25) v1(107.66,140.22) v1(107.66,138.18) v1(107.67,115.24) v1(107.76,136.24) v1(107.78,14.11) v1(107.78,13.63) v1(108.28,34.07) v1(108.27,31.79) v1(108.34,14.12) v1(108.42,50.88) v1(108.42,49.02) v1(108.35,13.64) v1(108.43,9.72) v1(108.45,47.08) v1(109.04,76.96) v1(109.04,74.93) v1(109.03,66.92) v1(109.06,81.03) v1(109.05,79) v1(109.45,159.29) v1(109.62,144.25) v1(109.68,156.41) v1(109.68,154.38) v1(109.68,152.35) v1(109.68,150.31) v1(109.68,148.28) v1(109.68,146.25) v1(109.69,142.25) v1(109.69,140.22) v1(109.69,138.18) v1(109.68,125.93) v1(109.68,123.9) v1(109.68,121.87) v1(109.68,119.83) v1(109.68,117.8) v1(109.7,115.24) v1(109.69,111.64) v1(109.79,136.24) v1(109.98,7.34) v1(109.98,6.57) v1(109.98,5.81) v1(110.24,39.67) v1(110.23,39.16) v1(110.39,7.98) v1(110.52,34.04) v1(110.51,14.08) v1(110.46,9.72) v1(110.62,31.53) v1(110.78,0.71) v1(111.08,109.66) v1(111.05,6.57) v1(111.05,5.81) v1(111.24,7.31) v1(111.34,144.53) v1(111.48,159.29) v1(111.53,43.09) v1(111.64,89.58) v1(111.71,156.41) v1(111.71,154.38) v1(111.71,152.35) v1(111.71,150.31) v1(111.71,148.28) v1(111.71,146.25) v1(111.72,142.25) v1(111.72,140.22) v1(111.72,138.18) v1(111.69,136.36) v1(111.71,125.93) v1(111.71,123.9) v1(111.71,121.87) v1(111.71,119.83) v1(111.71,117.8) v1(111.68,47.63) v1(111.73,39.61) v1(111.79,24.78) v1(111.88,103.29) v1(112.05,46.93) v1(112.13,45.51) v1(112.07,21.8) v1(112.17,49.35) v1(112.2,25.56) v1(112.44,104.94) v1(112.4,48.5) v1(112.5,53.15) v1(112.57,54.91) v1(112.61,40.87) v1(112.7,88.68) v1(112.73,50.54) v1(112.81,37.45) v1(112.94,112.65) v1(112.9,12.65) v1(113.14,109.62) v1(113.08,22.06) v1(113.24,101.49) v1(113.18,99.22) v1(113.3,107.79) v1(113.37,144.53) v1(113.51,159.29) v1(113.47,23.1) v1(113.57,75.68) v1(113.56,43.09) v1(113.74,156.41) v1(113.74,154.38) v1(113.74,152.35) v1(113.74,150.31) v1(113.74,148.28) v1(113.74,146.25) v1(113.72,136.36) v1(113.74,125.93) v1(113.74,123.9) v1(113.74,121.87) v1(113.74,119.83) v1(113.74,117.8) v1(113.71,95.14) v1(113.74,17.42) v1(113.75,142.25) v1(113.75,140.22) v1(113.75,138.18) v1(113.76,91.61) v1(113.76,25.27) v1(113.86,82.11) v1(113.88,40.2) v1(113.86,37.79) v1(113.87,11.64) v1(114.1,58.29) v1(114.16,34.49) v1(114.19,33.56) v1(114.21,21.83) v1(114.37,111.21) v1(114.39,27.92) v1(114.41,23.13) v1(114.5,53.35) v1(114.45,49.54) v1(114.51,26.43) v1(114.46,25.28) v1(114.59,28.9) v1(114.8,98.79) v1(114.77,27.2) v1(114.85,42.49) v1(114.91,13.46) v1(114.85,0.71) v1(114.97,83.84) v1(115.03,37.81) v1(115.15,102.2) v1(115.4,144.53) v1(115.36,107.75) v1(115.36,26.52) v1(115.47,51.56) v1(115.45,50.07) v1(115.55,159.29) v1(115.61,75.68) v1(115.69,136.23) v1(115.72,59.52) v1(115.68,57.22) v1(115.7,55.38) v1(115.72,53.42) v1(115.67,17.35) v1(115.77,156.41) v1(115.77,154.38) v1(115.77,152.35) v1(115.77,150.31) v1(115.77,148.28) v1(115.77,146.25) v1(115.75,142.28) v1(115.75,140.19) v1(115.81,138.03) v1(115.77,125.93) v1(115.77,123.9) v1(115.77,121.87) v1(115.77,119.83) v1(115.77,117.8) v1(115.81,109.77) v1(115.78,106.23) v1(115.78,104.2) v1(115.86,12.06) v1(116.03,83.34) v1(115.95,49.59) v1(116.08,94.03) v1(116.11,92.07) v1(116.09,29.04) v1(116.22,33.56) v1(116.19,21.55) v1(116.34,112.74) v1(116.26,20.06) v1(116.26,18.41) v1(116.35,112.3) v1(116.35,111.84) v1(116.38,88.28) v1(116.43,41.21) v1(116.68,38.5) v1(116.83,112.75) v1(116.84,112.31) v1(116.84,111.85) v1(116.88,0.71) v1(117,108.13) v1(117,106.1) v1(117,104.07) v1(117,102.03) v1(117,100) v1(117,97.97) v1(116.98,48.66) v1(117.15,34.22) v1(117.2,13.46) v1(117.44,144.53) v1(117.5,136.36) v1(117.5,134.32) v1(117.5,132.29) v1(117.46,109.02) v1(117.46,106.99) v1(117.46,104.96) v1(117.46,102.92) v1(117.46,100.89) v1(117.52,30.47) v1(117.52,21.92) v1(117.58,159.29) v1(117.61,9.05) v1(117.66,111.04) v1(117.69,41.72) v1(117.7,26.18) v1(117.8,156.41) v1(117.8,154.38) v1(117.8,152.35) v1(117.8,150.31) v1(117.8,148.28) v1(117.8,146.25) v1(117.78,142.28) v1(117.8,140.15) v1(117.8,138.12) v1(117.8,129.99) v1(117.8,127.96) v1(117.8,125.93) v1(117.8,123.9) v1(117.8,121.87) v1(117.8,117.8) v1(117.75,25.06) v1(117.75,23.54) v1(117.85,48.08) v1(117.94,32.46) v1(117.89,12.06) v1(118,38.53) v1(118.13,40.1) v1(118.21,95.9) v1(118.45,42.46) v1(118.58,64.85) v1(118.65,90.45) v1(118.71,63.28) v1(118.67,34.15) v1(118.72,13.46) v1(118.83,99.91) v1(118.91,0.71) v1(119.01,46.57) v1(119.09,86.52) v1(119.1,85.15) v1(119.24,92.4) v1(119.31,43.2) v1(119.47,144.53) v1(119.49,110.62) v1(119.49,38.42) v1(119.61,159.29) v1(119.84,156.41) v1(119.84,154.38) v1(119.84,152.35) v1(119.84,150.31) v1(119.84,148.28) v1(119.84,146.25) v1(119.84,140.15) v1(119.84,138.12) v1(119.84,136.09) v1(119.84,134.06) v1(119.84,132.03) v1(119.84,129.99) v1(119.84,127.96) v1(119.84,125.93) v1(119.84,123.9) v1(119.85,47.72) v1(119.85,45.68) v1(119.93,12.06) v1(120.06,43.95) v1(120.31,84.3) v1(120.25,34.72) v1(120.43,121.13) v1(120.6,65.11) v1(120.86,99.91) v1(120.94,79.92) v1(120.94,0.71) v1(121.14,141.86) v1(121.19,60.84) v1(121.47,111.04) v1(121.64,159.29) v1(121.77,13.46) v1(121.87,156.41) v1(121.87,154.38) v1(121.87,152.35) v1(121.87,150.31) v1(121.87,148.28) v1(121.87,146.25) v1(121.87,144.22) v1(121.87,121.87) v1(121.92,95.06) v1(121.93,91.47) v1(122.01,93.32) v1(122.02,79.92) v1(122.02,38.05) v1(121.96,12.06) v1(122.13,36.37) v1(122.57,141.95) v1(122.58,139.92) v1(122.58,137.89) v1(122.58,135.86) v1(122.58,133.83) v1(122.58,131.79) v1(122.58,129.76) v1(122.58,37.7) v1(123.03,126.23) v1(122.98,0.71) v1(123.08,79.91) v1(123.29,110.62) v1(123.3,13.46) v1(123.64,93.29) v1(123.64,38.02) v1(123.67,159.29) v1(123.84,40.1) v1(123.9,156.41) v1(123.9,154.38) v1(123.9,152.35) v1(123.9,150.31) v1(123.9,148.28) v1(123.9,146.25) v1(123.9,144.22) v1(123.9,142.19) v1(123.9,140.15) v1(123.9,138.12) v1(123.9,136.09) v1(123.9,134.06) v1(123.9,132.03) v1(123.9,129.99) v1(123.9,127.96) v1(123.9,123.9) v1(123.9,121.87) v1(123.99,12.06) v1(124.14,79.91) v1(124.32,118.99) v1(124.52,126.36) v1(124.47,124.79) v1(124.6,14) v1(124.68,99.91) v1(124.72,41.07) v1(124.8,93.91) v1(125.03,39.25) v1(125.01,0.71) v1(125.18,82.18) v1(125.19,16.06) v1(125.29,110.94) v1(125.29,42) v1(125.28,12.58) v1(125.71,159.29) v1(125.82,13.11) v1(125.93,156.41) v1(125.93,154.38) v1(125.93,152.35) v1(125.93,150.31) v1(125.93,148.28) v1(125.93,146.25) v1(125.93,144.22) v1(125.93,142.19) v1(125.93,140.15) v1(125.93,138.12) v1(125.93,136.09) v1(125.93,134.06) v1(125.93,132.03) v1(125.93,129.99) v1(125.93,127.96) v1(125.93,125.93) v1(125.91,123.36) v1(125.94,42.86) v1(125.96,124.92) v1(126.03,39.72) v1(126.3,43.9) v1(126.35,82.21) v1(126.36,13.65) v1(126.52,95.08) v1(126.67,29.78) v1(126.67,28.51) v1(126.67,27.24) v1(126.67,25.97) v1(126.67,24.7) v1(126.69,14.34) v1(126.83,79.88) v1(126.83,40.44) v1(126.89,11.94) v1(126.99,79.33) v1(126.98,77.89) v1(127.23,93.56) v1(127.29,121.87) v1(127.4,123.48) v1(127.42,110.62) v1(127.6,77.86) v1(127.63,41.18) v1(127.74,159.29) v1(127.94,29.78) v1(127.94,28.51) v1(127.94,27.24) v1(127.94,25.97) v1(127.94,24.7) v1(127.96,156.41) v1(127.96,154.38) v1(127.96,152.35) v1(127.96,150.31) v1(127.96,148.28) v1(127.96,146.25) v1(127.96,144.22) v1(127.96,142.19) v1(127.96,140.15) v1(127.96,138.12) v1(127.96,136.09) v1(127.96,134.06) v1(127.96,132.03) v1(127.96,129.99) v1(127.96,127.96) v1(127.96,125.93) v1(127.96,123.9) v1(127.96,117.8) v1(128.08,13.24) v1(128.43,41.9) v1(128.5,99.91) v1(128.91,16.77) v1(128.91,14.48) v1(128.87,12.02) v1(129.03,77.64) v1(128.98,17.33) v1(129.07,0.71) v1(129.21,29.78) v1(129.21,28.51) v1(129.21,27.24) v1(129.21,25.97) v1(129.21,24.7) v1(129.22,8.1) v1(129.22,7.34) v1(129.22,6.57) v1(129.22,5.81) v1(129.49,41.94) v1(129.52,18.4) v1(129.71,95.94) v1(129.77,159.29) v1(130,156.41) v1(130,154.38) v1(130,152.35) v1(130,150.31) v1(130,148.28) v1(130,146.25) v1(130,144.22) v1(130,142.19) v1(130,140.15) v1(130,138.12) v1(130,136.09) v1(130,134.06) v1(130,132.03) v1(130,129.99) v1(130,127.96) v1(130,125.93) v1(130,123.9) v1(130,121.87) v1(130,117.8) v1(129.99,13.02) v1(130.29,7.34) v1(130.29,6.57) v1(130.29,5.81) v1(130.38,16.73) v1(130.38,14.44) v1(130.48,29.78) v1(130.48,28.51) v1(130.48,27.24) v1(130.48,25.97) v1(130.48,24.7) v1(130.62,111.28) v1(130.64,81.08) v1(130.61,8.02) v1(130.77,17.87) v1(130.88,33.71) v1(131.17,80.99) v1(131.18,80.35) v1(131.15,8.56) v1(131.43,90.81) v1(131.43,86.67) v1(131.41,11.38) v1(131.63,91.61) v1(131.8,159.29) v1(131.75,29.78) v1(131.75,28.51) v1(131.75,27.24) v1(131.75,25.97) v1(131.75,24.7) v1(132.03,156.41) v1(132.03,154.38) v1(132.03,152.35) v1(132.03,150.31) v1(132.03,148.28) v1(132.03,146.25) v1(132.03,144.22) v1(132.03,142.19) v1(132.03,140.15) v1(132.03,138.12) v1(132.03,136.09) v1(132.03,134.06) v1(132.03,132.03) v1(132.03,129.99) v1(132.03,127.96) v1(132.03,125.93) v1(132.03,123.9) v1(132.03,121.87) v1(131.96,17.75) v1(132.31,99.91) v1(132.27,92.56) v1(132.4,33.96) v1(132.35,17.16) v1(132.53,90.82) v1(132.49,86.66) v1(132.62,83.96) v1(132.62,83) v1(132.57,12.26) v1(132.65,111.28) v1(132.83,16.57) v1(132.96,113.29) v1(133.07,33.95) v1(133.53,90.88) v1(133.56,109.64) v1(133.56,107.61) v1(133.56,105.58) v1(133.56,103.55) v1(133.56,101.52) v1(133.55,86.65) v1(133.69,33.92) v1(133.83,159.29) v1(133.84,83.54) v1(134.01,85.56) v1(134.06,156.41) v1(134.06,154.38) v1(134.06,152.35) v1(134.06,150.31) v1(134.06,148.28) v1(134.06,146.25) v1(134.06,144.22) v1(134.06,142.19) v1(134.06,140.15) v1(134.06,138.12) v1(134.06,136.09) v1(134.06,134.06) v1(134.06,132.03) v1(134.06,129.99) v1(134.06,127.96) v1(134.06,125.93) v1(134.06,123.9) v1(134.06,121.87) v1(134.06,117.8) v1(134.16,90.8) v1(134.24,86.66) v1(134.28,16.67) v1(135.24,86.65) v1(135.17,0.71) v1(135.82,60.66) v1(135.76,20.67) v1(135.87,159.29) v1(135.92,87.79) v1(136.02,90.73) v1(136,89.77) v1(136.02,88.74) v1(135.98,87.35) v1(136.09,156.41) v1(136.09,154.38) v1(136.09,152.35) v1(136.09,150.31) v1(136.09,148.28) v1(136.09,146.25) v1(136.09,144.22) v1(136.09,142.19) v1(136.09,140.15) v1(136.09,138.12) v1(136.09,136.09) v1(136.09,134.06) v1(136.09,125.93) v1(136.09,123.9) v1(136.09,121.87) v1(136.09,117.8) v1(136.75,72.45) v1(137.2,0.71) v1(137.9,159.29) v1(137.97,80.07) v1(138.12,156.41) v1(138.12,154.38) v1(138.12,152.35) v1(138.12,150.31) v1(138.12,148.28) v1(138.12,146.25) v1(138.12,144.22) v1(138.09,142.16) v1(138.09,140.13) v1(138.09,138.14) v1(138.09,136.11) v1(138.12,125.93) v1(138.12,123.9) v1(138.12,121.87) v1(138.12,117.8) v1(138.59,16.21) v1(138.72,69.52) v1(138.79,72.09) v1(139.2,81.69) v1(139.23,0.71) v1(139.55,111.18) v1(139.6,109.15) v1(139.6,107.12) v1(139.6,105.08) v1(139.6,103.05) v1(139.6,101.02) v1(139.55,98.99) v1(139.93,159.29) v1(139.87,90.26) v1(140.13,142.16) v1(140.13,140.13) v1(140.13,138.14) v1(140.13,136.11) v1(140.12,96.68) v1(140.16,156.41) v1(140.16,154.38) v1(140.16,152.35) v1(140.16,150.31) v1(140.16,148.28) v1(140.16,146.25) v1(140.16,144.22) v1(140.16,125.93) v1(140.16,123.9) v1(140.16,121.87) v1(140.16,117.8) v1(140.42,78.31) v1(140.39,27.93) v1(140.51,36.06) v1(140.51,34.02) v1(140.51,29.96) v1(141.12,37.99) v1(141.33,85.8) v1(141.26,0.71) v1(141.38,110.76) v1(141.35,92.47) v1(141.56,73.31) v1(141.73,56.58) v1(141.87,67.83) v1(141.96,159.29) v1(142.05,144.11) v1(142.05,142.08) v1(142.05,140.04) v1(142.19,156.41) v1(142.19,154.38) v1(142.19,152.35) v1(142.19,150.31) v1(142.19,148.28) v1(142.19,146.25) v1(142.18,138.15) v1(142.19,136.09) v1(142.19,125.93) v1(142.19,123.9) v1(142.19,121.87) v1(142.19,117.8) v1(142.23,93.08) v1(142.23,35.36) v1(142.23,33.32) v1(142.25,18.57) v1(142.25,16.54) v1(142.41,99.89) v1(142.41,79.19) v1(142.45,78.31) v1(142.57,73.64) v1(142.85,85.94) v1(143.05,79.85) v1(143.08,13.63) v1(143.19,86.25) v1(143.31,84.84) v1(143.3,0.71) v1(143.36,111.18) v1(143.62,20.08) v1(143.86,9.2) v1(143.99,159.29) v1(143.97,96.68) v1(144.08,144.11) v1(144.08,142.08) v1(144.08,140.04) v1(144.14,79.87) v1(144.22,156.41) v1(144.22,154.38) v1(144.22,152.35) v1(144.22,150.31) v1(144.22,148.28) v1(144.22,146.25) v1(144.22,138.12) v1(144.22,136.09) v1(144.22,125.93) v1(144.22,123.9) v1(144.22,121.87) v1(144.22,117.8) v1(144.25,93.26) v1(144.94,94.01) v1(144.9,30.5) v1(145.13,79.86) v1(145.15,85.71) v1(145.33,0.71) v1(145.5,110.95) v1(145.65,51.3) v1(145.65,20.08) v1(145.79,56.55) v1(145.89,9.26) v1(146.03,159.29) v1(146.11,144.11) v1(146.11,142.08) v1(146.11,140.04) v1(146.21,79.84) v1(146.25,156.41) v1(146.25,154.38) v1(146.25,152.35) v1(146.25,150.31) v1(146.25,148.28) v1(146.25,146.25) v1(146.26,41.85) v1(146.45,138.15) v1(146.48,60.82) v1(146.59,99.89) v1(146.63,94.33) v1(146.67,73.69) v1(146.71,55.87) v1(146.68,37.49) v1(146.79,136.14) v1(146.91,57.89) v1(146.93,30.5) v1(147.14,75.82) v1(147.2,122.08) v1(147.19,111.19) v1(147.33,118.02) v1(147.3,82.3) v1(147.37,94.32) v1(147.68,51.22) v1(147.68,20.08) v1(147.77,96.66) v1(148.06,159.29) v1(148.15,144.11) v1(148.15,142.08) v1(148.15,140.04) v1(148.28,156.41) v1(148.28,154.38) v1(148.28,152.35) v1(148.28,150.31) v1(148.28,148.28) v1(148.28,146.25) v1(148.28,136.09) v1(148.29,95.07) v1(148.29,41.85) v1(148.4,99.46) v1(148.36,82.3) v1(148.39,77.96) v1(148.47,122.43) v1(148.47,118.37) v1(148.46,8.1) v1(148.46,7.34) v1(148.46,6.57) v1(148.46,5.81) v1(148.71,37.49) v1(148.87,82.95) v1(149.01,93.64) v1(148.96,30.5) v1(149.3,110.92) v1(149.38,43.56) v1(149.39,0.71) v1(149.53,8.1) v1(149.53,7.34) v1(149.53,6.57) v1(149.53,5.81) v1(150.09,159.29) v1(150.32,156.41) v1(150.32,154.38) v1(150.32,152.35) v1(150.32,150.31) v1(150.32,148.28) v1(150.32,146.25) v1(150.32,142.19) v1(150.32,138.12) v1(150.32,136.09) v1(150.43,93.37) v1(150.58,139.17) v1(150.55,129.86) v1(150.65,94.22) v1(150.75,37.49) v1(151,30.5) v1(151.63,96.7) v1(152.12,159.29) v1(152.24,88.22) v1(152.35,152.35) v1(152.35,150.31) v1(152.35,148.28) v1(152.35,146.25) v1(152.35,144.22) v1(152.35,142.19) v1(152.35,140.15) v1(152.35,138.12) v1(152.35,136.09) v1(152.35,134.06) v1(152.35,132.03) v1(152.35,129.99) v1(152.35,127.96) v1(152.35,125.93) v1(152.35,123.9) v1(152.94,139.22) v1(152.94,137.19) v1(152.94,135.16) v1(152.94,133.12) v1(152.94,131.09) v1(152.94,129.06) v1(152.94,127.03) v1(152.94,125) v1(152.94,122.96) v1(152.94,120.93) v1(152.94,118.9) v1(153.34,141.1) v1(153.47,86.72) v1(153.46,0.71) v1(154.08,139.21) v1(154.08,137.17) v1(154.08,135.14) v1(154.08,133.11) v1(154.08,131.08) v1(154.08,129.05) v1(154.08,127.01) v1(154.08,124.98) v1(154.08,122.95) v1(154.08,120.92) v1(154.08,118.89) v1(154.15,159.29) v1(154.38,150.31) v1(154.38,148.28) v1(154.38,146.25) v1(154.38,144.22) v1(154.38,142.19) v1(154.38,140.15) v1(154.38,138.12) v1(154.38,136.09) v1(154.38,134.06) v1(154.38,132.03) v1(154.38,129.99) v1(154.38,127.96) v1(154.38,125.93) v1(154.38,123.9) v1(154.38,121.87) v1(155.01,91.01) v1(155.06,30.5) v1(155.49,0.71) v1(155.8,86.68) v1(156.1,87.96) v1(156.17,159.27) v1(156.41,150.31) v1(156.41,148.28) v1(156.41,146.25) v1(156.41,144.22) v1(156.41,142.19) v1(156.41,140.15) v1(156.41,138.12) v1(156.41,136.09) v1(156.41,134.06) v1(156.41,132.03) v1(156.41,129.99) v1(156.41,127.96) v1(156.41,125.93) v1(156.41,123.9) v1(156.41,121.87) v1(156.41,119.83) v1(156.41,117.8) v1(156.41,115.77) v1(156.41,113.74) v1(157.09,30.5) v1(157.47,1.18) v1(157.69,86.7) v1(157.79,19.62) v1(158.03,158.4) v1(158,90.58) v1(158,88.89) v1(158,87.29) v1(158.05,17.6) v1(158.05,15.57) v1(158.36,36.15) v1(158.36,34.11) v1(158.36,32.08) v1(158.8,2.71) v1(159.01,156.63) v1(159.07,154.59) v1(159.07,152.56) v1(159.07,150.53) v1(159.07,148.5) v1(159.07,146.47) v1(159.07,144.43) v1(159.07,142.4) v1(159.07,140.37) v1(159.07,138.34) v1(159.07,136.31) v1(159.07,134.27) v1(159.07,132.24) v1(159.07,130.21) v1(159.07,128.18) v1(159.07,126.15) v1(159.07,124.11) v1(159.07,122.08) v1(159.07,120.05) v1(159.07,118.02) v1(159.07,115.99) v1(159.07,113.95) v1(159.07,111.92) v1(159.07,109.89) v1(159.07,107.86) v1(159.07,105.83) v1(159.07,103.79) v1(159.07,101.76) v1(159.07,99.73) v1(159.07,97.7) v1(159.07,95.67) v1(159.07,93.63) v1(159.07,91.6) v1(159.07,89.57) v1(159.07,87.54) v1(159.07,85.51) v1(159.07,83.47) v1(159.07,81.44) v1(159.07,79.41) v1(159.07,77.38) v1(159.07,75.35) v1(159.07,57.55) v1(159.07,55.52) v1(159.07,53.49) v1(159.07,51.46) v1(159.07,49.42) v1(159.07,47.39) v1(159.07,45.36) v1(159.07,43.33) v1(159.07,41.3) v1(159.07,39.26) v1(159.07,37.23) v1(159.07,35.2) v1(159.07,33.17) v1(159.07,31.14) v1(159.07,29.1) v1(159.07,27.07) v1(159.07,25.04) v1(159.07,23.01) v1(159.07,20.98) v1(159.07,18.94) v1(159.07,16.91) v1(159.07,14.88) v1(159.07,12.85) v1(159.07,6.75) v1(159.07,4.72) v2(1.39,99.21) v2(1.39,98.21) v2(2.17,114.41) v2(2.17,113.41) v2(2.17,112.41) v2(2.17,111.41) v2(2.17,110.41) v2(2.17,109.41) v2(3.17,111.41) v2(3.17,110.41) v2(3.17,109.41) v2(4.17,111.41) v2(4.77,14.96) v2(4.77,13.96) v2(4.77,12.96) v2(5.17,111.41) v2(5.77,14.96) v2(5.77,13.96) v2(5.77,12.96) v2(6.17,111.41) v2(6.77,14.96) v2(6.77,13.96) v2(6.77,12.96) v2(7.17,111.41) v2(8.17,114.41) v2(8.17,113.41) v2(8.17,112.41) v2(8.17,111.41) v2(8.39,98.21) v2(9.08,100.09) v2(9.17,114.41) v2(9.17,113.41) v2(9.17,112.41) v2(9.17,111.41) v2(10.08,100.09) v2(10.17,112.41) v2(10.17,111.41) v2(11.17,112.41) v2(11.17,111.41) v2(12.17,114.41) v2(12.17,113.41) v2(12.17,112.41) v2(12.17,111.41) v2(13.17,114.41) v2(13.17,113.41) v2(13.17,112.41) v2(13.17,111.41) v2(14.53,102.73) v2(14.53,101.73) v2(14.53,100.73) v2(15.53,102.73) v2(15.53,101.73) v2(15.53,100.73) v2(16.53,102.73) v2(16.53,101.73) v2(16.53,100.73) v2(17.53,102.73) v2(17.53,101.73) v2(17.53,100.73) v2(18.53,102.73) v2(18.53,101.73) v2(18.53,100.73) v2(19.07,119.94) v2(19.07,118.91) v2(19.07,117.91) v2(19.53,102.73) v2(19.53,101.73) v2(19.53,100.73) v2(20.07,118.91) v2(20.07,117.91) v2(20.37,4.04) v2(20.37,3.04) v2(20.37,2.04) v2(20.53,102.73) v2(20.53,101.73) v2(20.53,100.73) v2(21.07,117.91) v2(21.37,4.04) v2(21.37,3.04) v2(21.37,2.04) v2(21.53,102.73) v2(21.53,101.73) v2(21.53,100.73) v2(22.37,4.04) v2(22.37,3.04) v2(22.37,2.04) v2(22.53,102.73) v2(22.53,101.73) v2(22.53,100.73) v2(23.53,102.73) v2(23.53,101.73) v2(23.53,100.73) v2(27.79,111.12) v2(28.18,119.56) v2(28.18,118.56) v2(28.69,102.77) v2(28.69,101.77) v2(28.69,100.77) v2(29.16,119.54) v2(29.16,118.54) v2(29.71,103.76) v2(29.69,102.77) v2(29.69,101.77) v2(29.69,100.77) v2(30.13,106.88) v2(30.15,119.53) v2(30.15,118.53) v2(30.71,103.76) v2(31.71,103.76) v2(32.71,103.76) v2(33.08,106.76) v2(33.06,105.71) v2(33.71,103.76) v2(34,24.82) v2(34.11,105.7) v2(34.31,118.9) v2(34.31,117.9) v2(35.04,24.82) v2(35.26,118.91) v2(35.26,117.91) v2(35.33,108.89) v2(36.28,118.93) v2(36.28,117.93) v2(37.26,118.91) v2(37.26,117.91) v2(37.98,111.39) v2(37.99,19.82) v2(38.17,118.91) v2(38.17,117.91) v2(38.49,32.75) v2(38.48,25.75) v2(38.47,24.68) v2(38.47,23.63) v2(38.52,21.78) v2(39.65,3.98) v2(39.65,2.98) v2(39.65,1.98) v2(40.31,26) v2(40.41,23.02) v2(40.65,3.98) v2(40.65,2.98) v2(40.65,1.98) v2(40.82,31.94) v2(41.65,3.98) v2(41.65,2.98) v2(41.65,1.98) v2(43.35,33.67) v2(44.17,33.67) v2(44.47,22.9) v2(46.56,31.77) v2(46.73,13.1) v2(47.65,13.1) v2(48.35,22.95) v2(48.74,27) v2(49.73,24.23) v2(51.81,19.02) v2(52.63,19.04) v2(54.67,24.43) v2(55.71,24.43) v2(55.7,21.62) v2(56.32,33.46) v2(56.52,13.6) v2(58.15,21.12) v2(58.9,3.96) v2(58.9,2.96) v2(58.9,1.96) v2(59.4,26.6) v2(59.42,25.21) v2(59.9,3.96) v2(59.9,2.96) v2(59.9,1.96) v2(60.9,3.96) v2(60.9,2.96) v2(60.9,1.96) v2(65.92,11.91) v2(66.9,11.9) v2(78.04,3.77) v2(78.04,2.77) v2(78.04,1.77) v2(79.04,3.77) v2(79.04,2.77) v2(79.04,1.77) v2(80.04,3.77) v2(80.04,2.77) v2(80.04,1.77) v2(80.48,142) v2(82.52,142.01) v2(97.22,3.73) v2(97.22,2.73) v2(97.22,1.73) v2(98.22,3.73) v2(98.22,2.73) v2(98.22,1.73) v2(99.22,3.73) v2(99.22,2.73) v2(99.22,1.73) v2(116.6,4.1) v2(116.6,3.1) v2(116.6,2.1) v2(117.1,59.58) v2(117.1,58.58) v2(117.1,57.58) v2(117.1,56.58) v2(117.1,55.58) v2(117.1,54.58) v2(117.1,53.58) v2(117.1,52.58) v2(117.1,51.58) v2(117.1,50.58) v2(117.6,4.1) v2(117.6,3.1) v2(117.6,2.1) v2(118.1,59.58) v2(118.1,58.58) v2(118.1,57.58) v2(118.1,56.58) v2(118.1,55.58) v2(118.1,54.58) v2(118.1,53.58) v2(118.1,52.58) v2(118.1,51.58) v2(118.1,50.58) v2(118.41,24.9) v2(118.6,4.1) v2(118.6,3.1) v2(118.6,2.1) v2(118.81,69.3) v2(118.81,68.3) v2(118.81,67.3) v2(118.81,66.3) v2(119.1,51.58) v2(119.1,50.58) v2(119.65,25.2) v2(119.81,69.3) v2(119.81,68.3) v2(119.81,67.3) v2(119.81,66.3) v2(119.78,62.34) v2(120.1,51.58) v2(120.1,50.58) v2(120.81,67.3) v2(120.81,66.3) v2(120.78,63.34) v2(120.78,62.34) v2(121.81,66.3) v2(121.78,64.34) v2(121.78,63.34) v2(121.78,62.34) v2(122.81,67.3) v2(122.81,66.3) v2(122.78,64.34) v2(122.78,63.34) v2(122.78,62.34) v2(122.98,32.84) v2(122.98,24.76) v2(122.99,21.67) v2(123.06,29.63) v2(123.81,67.3) v2(123.81,66.3) v2(123.78,64.34) v2(123.78,63.34) v2(123.78,62.34) v2(124.46,31.2) v2(124.63,88.42) v2(124.74,16.93) v2(124.81,67.3) v2(124.81,66.3) v2(124.78,64.34) v2(124.78,63.34) v2(124.78,62.34) v2(124.91,87.13) v2(125.63,27.14) v2(125.83,89.42) v2(125.82,88.41) v2(125.81,67.3) v2(125.81,66.3) v2(125.78,64.34) v2(125.78,63.34) v2(126.81,67.3) v2(126.81,66.3) v2(126.78,64.34) v2(126.78,63.34) v2(127.09,88.42) v2(127.55,55.37) v2(127.55,54.37) v2(127.55,53.37) v2(127.55,52.37) v2(127.55,51.37) v2(127.55,50.37) v2(127.81,67.3) v2(127.81,66.3) v2(127.78,64.34) v2(127.78,63.34) v2(127.87,33.92) v2(128.27,23.15) v2(128.55,55.37) v2(128.55,54.37) v2(128.55,53.37) v2(128.55,52.37) v2(128.55,51.37) v2(128.55,50.37) v2(128.57,49.35) v2(128.71,33.91) v2(128.81,67.3) v2(128.81,66.3) v2(128.78,64.34) v2(128.78,63.34) v2(128.79,31.57) v2(129.55,55.37) v2(129.55,54.37) v2(129.55,53.37) v2(129.55,52.37) v2(129.55,51.37) v2(129.55,50.37) v2(129.55,49.37) v2(129.81,67.3) v2(129.81,66.3) v2(129.78,64.34) v2(129.78,63.34) v2(130.55,53.37) v2(130.55,52.37) v2(130.55,51.37) v2(130.78,64.34) v2(130.78,63.34) v2(131.55,53.37) v2(131.55,52.37) v2(131.55,51.37) v2(131.78,64.34) v2(131.78,63.34) v2(131.78,62.34) v2(131.95,23.37) v2(132.55,53.37) v2(132.55,52.37) v2(132.55,51.37) v2(132.78,64.34) v2(132.78,63.34) v2(132.78,62.34) v2(133.16,31.61) v2(133.31,25.11) v2(133.31,23.58) v2(133.27,22.51) v2(133.43,27.14) v2(133.55,53.37) v2(133.55,52.37) v2(133.55,51.37) v2(133.78,64.34) v2(134.55,53.37) v2(134.55,52.37) v2(135.55,53.37) v2(135.55,52.37) v2(135.87,4.16) v2(135.87,3.16) v2(135.87,2.16) v2(136.55,53.37) v2(136.87,4.16) v2(136.87,3.16) v2(136.87,2.16) v2(137.55,53.37) v2(137.55,52.37) v2(137.78,64.34) v2(137.78,63.34) v2(137.87,4.16) v2(137.87,3.16) v2(137.87,2.16) v2(138.58,75.27) v2(138.55,53.37) v2(138.55,52.37) v2(138.78,64.34) v2(138.78,63.34) v2(139.55,53.37) v2(139.55,52.37) v2(139.55,51.37) v2(140.29,62.46) v2(140.55,53.37) v2(140.55,52.37) v2(140.55,51.37) v2(140.73,73.36) v2(140.74,28.4) v2(140.89,33.63) v2(141.19,62.46) v2(141.55,53.37) v2(141.55,52.37) v2(141.55,51.37) v2(142.18,71.58) v2(142.18,70.26) v2(142.2,68.78) v2(142.15,60.94) v2(142.15,59.62) v2(142.17,58.13) v2(142.95,29.42) v2(142.95,28.42) v2(142.95,27.42) v2(142.95,26.42) v2(142.95,25.42) v2(142.95,24.42) v2(143.89,71.58) v2(143.89,70.26) v2(143.86,60.94) v2(143.95,29.42) v2(143.95,28.42) v2(143.95,27.42) v2(143.95,26.42) v2(143.95,25.42) v2(143.95,24.42) v2(144.95,29.42) v2(144.95,28.42) v2(144.95,27.42) v2(144.95,26.42) v2(144.95,25.42) v2(144.95,24.42) v2(146.54,89.35) v2(146.56,88.28) v2(147.56,65.81) v2(147.83,89.33) v2(147.85,88.26) v2(148.44,66.63) v2(148.44,65.82) v2(148.62,55.97) v2(149.15,89.3) v2(149.17,88.23) v2(149.61,55.96) v2(149.74,51.27) v2(149.74,50.27) v2(149.83,64.56) v2(149.83,63.74) v2(149.82,62.91) v2(149.79,47.04) v2(149.79,46.04) v2(153.63,55.93) v2(154.61,55.91) v2(155.61,55.91) v2(158.43,57.46) v2(158.43,56.46) v2(158.43,55.46) v2(158.43,54.46) v2(158.74,67.63) v2(158.74,66.63) v2(158.74,65.63) v2(158.74,64.63) v2(158.74,63.63)
